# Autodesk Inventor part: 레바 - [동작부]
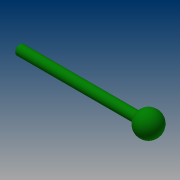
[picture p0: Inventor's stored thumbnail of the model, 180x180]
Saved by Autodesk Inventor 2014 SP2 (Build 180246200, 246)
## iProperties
Created: 2015-12
Part Number: 레바 - [동작부]
Material: 스테인리스강
Document SubType Name: Modeling
Designer: mduedu
Density: 8.08 g/cm^3
Mass: 30.7693 g
Surface Area: 20.8622 cm^2
Volume: 3.80808 cm^3
Appearance: 진녹색
Author: mduedu
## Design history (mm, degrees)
sketch "스케치1"
  geometry: C1 r 3 at (0, 0); 1 further point
  constraints: 1 centre point, 1 coincident
  dimensions: "d0" = 6 diameter of C1
extrude "돌출1" new body sketch "스케치1" distance "d1" = 80; taper "d2" = 0 deg
sketch "스케치2"
  geometry: L1 (7.5, 0)-(-6, 0); L2 (-6, 4.5)-(-6, 0); A1 r 7.5 centre (0, 0) between (7.5, 0) and (-6, 4.5); 2 further points
  constraints: 4 end point, 2 coincident, 2 point on circle, 1 centre point, 1 horizontal, 1 perpendicular, 1 point on line
  dimensions: "d3" = 15 diameter of A1; "d10" = 6 distance from line of L2 point (0, 0)
revolve "회전1" sketch "스케치2" stored, may be unused: angle "d4" = 90 deg
chamfer "모따기1" distance "d7" = 0.5; stored, may be unused: second distance "d8" = 2, angle "d9" = 45 deg
fillet "모깎기2" dims "d11" = 0.3
node "솔리드1"
